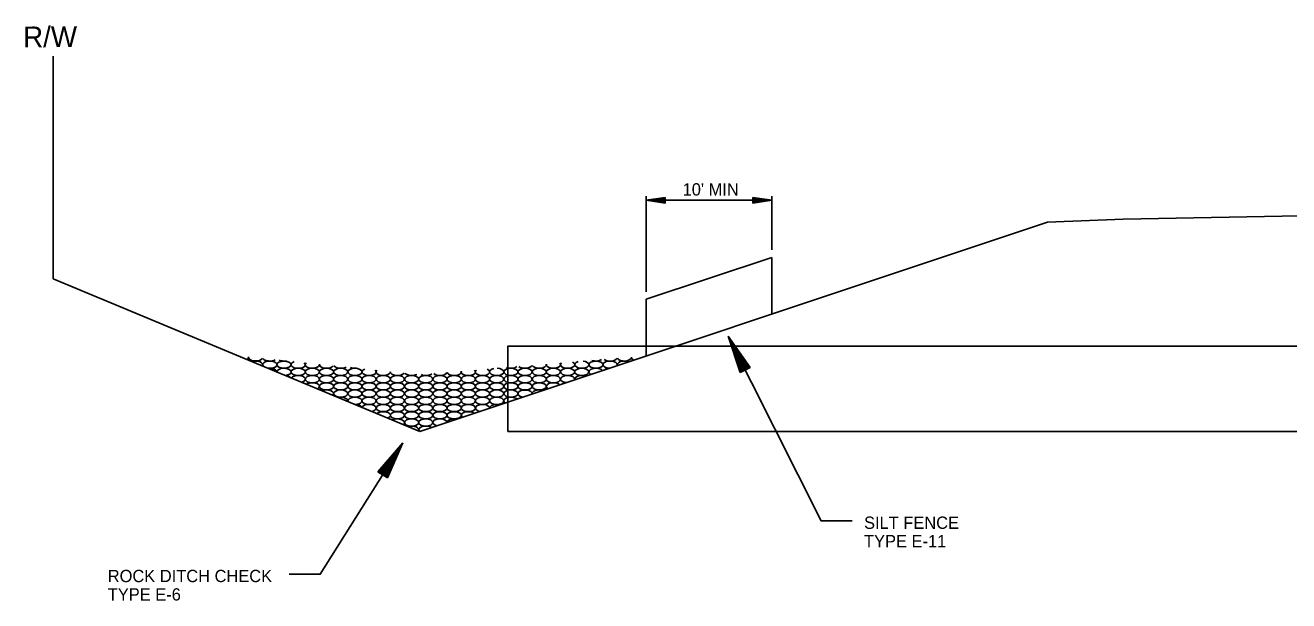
# Model space of a CAD drawing. Extents: x 3575 to 11445, y 9479 to 13278.
# Drawn here: x 3575 to 4243, y 12956 to 13260 of the extents above; entities that cross this region are included whole.
import ezdxf

# ---------------------------------------------------------------- set-up
doc = ezdxf.new("R2010")
doc.units = 0
for name, color, linetype in [('Agg Base Course Text', 7, 'Continuous'), ('Aggregate Base Course', 7, 'Continuous'), ('Default', 7, 'Continuous'), ('R_Culvert', 7, 'Continuous'), ('R_Dimension', 7, 'Continuous'), ('R_ROW', 7, 'Continuous'), ('R_ROW Annot Labels', 7, 'Continuous'), ('STAMP_PE_CRAFTON-SIGNATURE', 7, 'Continuous')]:
    doc.layers.add(name, color=color, linetype=linetype)

msp = doc.modelspace()

# ---------------------------------------------------------------- linework, layer by layer
at = {"layer": 'Agg Base Course Text'}
for points in [[(4012.16, 12997.7), (3995.71, 12997.7), (3946.53, 13095.5)], [(3714.29, 12969.51), (3730.74, 12969.51), (3774.5, 13038.99)]]:
    msp.add_lwpolyline(points, dxfattribs=at)
at = {"layer": 'Aggregate Base Course'}
for centre, start_param, end_param in [((3689.08, 13084.23), 2.514604, 3.290239), ((3696.58, 13084.23), 6.138963, 9.16605), ((3891.58, 13084.23), 0.234109, 3.231422), ((3899.08, 13084.23), 6.192018, 7.124953), ((3899.08, 13084.23), 3.457622, 3.556698), ((3906.58, 13084.23), 5.83504, 5.875133), ((3696.58, 13080.41), 2.805024, 5.249722), ((3704.08, 13080.41), 1.278334, 6.776412), ((3704.08, 13084.23), 0.273657, 2.464986), ((3704.08, 13076.58), 3.131558, 4.923189), ((3711.58, 13076.58), 1.761439, 6.293307), ((3711.58, 13084.23), 0.829284, 1.909359), ((3719.08, 13080.41), 5.30404, 10.000973), ((3726.58, 13080.41), 5.775562, 9.529451), ((3734.08, 13080.41), 6.180718, 9.124295), ((3741.58, 13080.41), 0.321062, 2.417581), ((3749.08, 13080.41), 0.916722, 1.82192), ((3756.58, 13076.58), 5.360895, 9.944118), ((3764.08, 13076.58), 5.818933, 9.48608), ((3809.08, 13076.58), 6.111119, 9.920782), ((3816.58, 13076.58), 5.737074, 10.294828), ((3824.08, 13076.58), 5.107712, 10.924189), ((3831.58, 13080.41), 0.907562, 2.557968), ((3839.08, 13080.41), 0.525834, 2.939697), ((3846.58, 13080.41), 0.195345, 3.270186), ((3854.08, 13080.41), 6.151816, 9.880086), ((3861.58, 13080.41), 5.786986, 10.244916), ((3869.08, 13080.41), 5.239177, 10.792724), ((3876.58, 13076.58), 3.525059, 7.057516), ((3876.58, 13084.23), 0.961624, 2.503906), ((3884.08, 13080.41), 2.835165, 7.74741), ((3884.08, 13076.58), 4.840285, 5.74229), ((3884.08, 13084.23), 0.567598, 2.897933), ((3891.58, 13080.41), 4.046304, 6.536271), ((3711.58, 13072.76), 3.595841, 4.458905), ((3719.08, 13072.76), 2.091472, 5.963275), ((3726.58, 13068.93), 2.382906, 5.67184), ((3771.58, 13076.58), 6.222647, 9.082366), ((3779.08, 13076.58), 0.369799, 2.368843), ((3786.58, 13076.58), 0.856077, 2.609454), ((3794.08, 13076.58), 0.484724, 2.980806), ((3801.58, 13076.58), 0.15663, 3.3089), ((3854.08, 13068.93), 3.591606, 6.755501), ((3861.58, 13072.76), 2.933177, 7.649398), ((3861.58, 13068.93), 5.028509, 5.554066), ((3869.08, 13072.76), 4.116502, 6.466073), ((3734.08, 13065.11), 2.667988, 5.386758), ((3839.08, 13065.11), 3.022345, 7.56023), ((3846.58, 13065.11), 4.188827, 6.393748), ((3854.08, 13068.93), 0.472316, 0.707784), ((3741.58, 13061.28), 2.972437, 5.082309), ((3749.08, 13061.28), 1.574453, 6.480293), ((3749.08, 13057.46), 3.34603, 4.708717), ((3756.58, 13057.46), 1.946039, 6.108707), ((3816.58, 13057.46), 3.105273, 7.477302), ((3824.08, 13057.46), 4.263908, 6.318667), ((3831.58, 13061.28), 3.657582, 6.924993), ((3764.08, 13053.63), 2.249906, 5.80484), ((3771.58, 13049.81), 2.534898, 5.519849), ((3794.08, 13049.81), 3.18359, 7.398985), ((3801.58, 13049.81), 4.34257, 6.240005), ((3809.08, 13053.63), 3.723285, 6.85929), ((3779.08, 13045.98), 2.826651, 5.228095), ((3786.58, 13045.98), 3.789, 6.726478)]:
    msp.add_ellipse(centre, major_axis=(-3.75, 0), ratio=0.51, start_param=start_param, end_param=end_param, dxfattribs=at)
for centre in [(3711.58, 13080.41), (3719.08, 13076.58), (3726.58, 13076.58), (3734.08, 13076.58), (3741.58, 13076.58), (3749.08, 13076.58), (3831.58, 13076.58), (3839.08, 13076.58), (3846.58, 13076.58), (3854.08, 13076.58), (3861.58, 13076.58), (3869.08, 13076.58), (3876.58, 13080.41), (3726.58, 13072.76), (3734.08, 13072.76), (3734.08, 13068.93), (3741.58, 13072.76), (3741.58, 13068.93), (3749.08, 13072.76), (3749.08, 13068.93), (3756.58, 13072.76), (3756.58, 13068.93), (3764.08, 13072.76), (3764.08, 13068.93), (3771.58, 13072.76), (3771.58, 13068.93), (3779.08, 13072.76), (3779.08, 13068.93), (3786.58, 13072.76), (3786.58, 13068.93), (3794.08, 13072.76), (3794.08, 13068.93), (3801.58, 13072.76), (3801.58, 13068.93), (3809.08, 13072.76), (3809.08, 13068.93), (3816.58, 13072.76), (3816.58, 13068.93), (3824.08, 13072.76), (3824.08, 13068.93), (3831.58, 13072.76), (3831.58, 13068.93), (3839.08, 13072.76), (3839.08, 13068.93), (3846.58, 13072.76), (3846.58, 13068.93), (3854.08, 13072.76), (3741.58, 13065.11), (3749.08, 13065.11), (3756.58, 13065.11), (3764.08, 13065.11), (3771.58, 13065.11), (3779.08, 13065.11), (3786.58, 13065.11), (3794.08, 13065.11), (3801.58, 13065.11), (3809.08, 13065.11), (3816.58, 13065.11), (3824.08, 13065.11), (3831.58, 13065.11), (3756.58, 13061.28), (3764.08, 13061.28), (3764.08, 13057.46), (3771.58, 13061.28), (3771.58, 13057.46), (3779.08, 13061.28), (3779.08, 13057.46), (3786.58, 13061.28), (3786.58, 13057.46), (3794.08, 13061.28), (3794.08, 13057.46), (3801.58, 13061.28), (3801.58, 13057.46), (3809.08, 13061.28), (3809.08, 13057.46), (3816.58, 13061.28), (3824.08, 13061.28), (3771.58, 13053.63), (3779.08, 13053.63), (3779.08, 13049.81), (3786.58, 13053.63), (3786.58, 13049.81), (3794.08, 13053.63), (3801.58, 13053.63)]:
    msp.add_ellipse(centre, major_axis=(-3.75, 0), ratio=0.51, dxfattribs=at)
at = {"layer": 'Default'}
for p, q in [((4265.38, 13159.56), (4155.4, 13157.36)), ((3783.4, 13045.08), (4115.44, 13155.76)), ((4155.4, 13157.36), (4115.44, 13155.76)), ((3969.62, 13137.15), (3969.62, 13107.15)), ((3783.4, 13045.08), (3589.55, 13125.85))]:
    msp.add_line(p, q, dxfattribs=at)
msp.add_lwpolyline([(3903.21, 13085.02), (3903.21, 13115.02), (3969.62, 13137.15)], dxfattribs=at)
at = {"layer": 'R_Culvert'}
msp.add_lwpolyline([(3830, 13045.08), (4700.77, 13045.08), (4700.77, 13090.24), (3830, 13090.24)], close=True, dxfattribs=at)
at = {"layer": 'R_Dimension'}
for p, q in [((3903.21, 13119.02), (3903.21, 13169.64)), ((3913.21, 13168.87), (3903.21, 13167.37)), ((3903.21, 13167.37), (3969.62, 13167.37)), ((3913.21, 13165.87), (3903.21, 13167.37)), ((3913.21, 13168.62), (3904.88, 13167.37)), ((3913.21, 13166.12), (3904.88, 13167.37)), ((3913.21, 13168.36), (3906.6, 13167.37)), ((3913.21, 13166.37), (3906.6, 13167.37)), ((3913.21, 13168.11), (3908.26, 13167.37)), ((3913.21, 13166.62), (3908.26, 13167.37)), ((3913.21, 13167.86), (3909.96, 13167.37)), ((3913.21, 13166.88), (3909.96, 13167.37)), ((3913.21, 13167.6), (3911.63, 13167.37)), ((3913.21, 13167.13), (3911.63, 13167.37)), ((3913.21, 13165.87), (3913.21, 13168.87)), ((3959.62, 13168.87), (3969.62, 13167.37)), ((3959.62, 13168.87), (3959.62, 13165.87)), ((3959.62, 13168.62), (3967.95, 13167.37)), ((3959.62, 13168.36), (3966.23, 13167.37)), ((3959.62, 13168.11), (3964.56, 13167.37)), ((3959.62, 13167.85), (3962.87, 13167.37)), ((3959.62, 13167.6), (3961.2, 13167.37)), ((3959.62, 13165.87), (3969.62, 13167.37)), ((3959.62, 13166.88), (3962.87, 13167.37)), ((3959.62, 13166.37), (3966.23, 13167.37)), ((3959.62, 13166.12), (3967.95, 13167.37)), ((3959.62, 13166.62), (3964.56, 13167.37)), ((3959.62, 13167.13), (3961.2, 13167.37)), ((3969.62, 13169.64), (3969.62, 13141.15))]:
    msp.add_line(p, q, dxfattribs=at)
at = {"layer": 'R_ROW'}
msp.add_line((3589.55, 13125.85), (3589.55, 13243.58), dxfattribs=at)
at = {"layer": 'STAMP_PE_CRAFTON-SIGNATURE'}
for p, q in [((3952.83, 13076.28), (3946.53, 13095.5)), ((3958.19, 13078.98), (3946.53, 13095.5)), ((3953.28, 13076.51), (3948.03, 13092.51)), ((3957.75, 13078.75), (3948.03, 13092.51)), ((3957.29, 13078.52), (3949.57, 13089.44)), ((3953.74, 13076.73), (3949.57, 13089.44)), ((3954.18, 13076.96), (3951.07, 13086.46)), ((3956.84, 13078.3), (3951.07, 13086.46)), ((3956.39, 13078.07), (3952.59, 13083.44)), ((3954.65, 13077.19), (3952.59, 13083.44)), ((3952.83, 13076.28), (3958.19, 13078.98)), ((3955.93, 13077.84), (3954.09, 13080.45)), ((3955.09, 13077.42), (3954.09, 13080.45)), ((3761.3, 13023.67), (3774.5, 13038.99)), ((3766.38, 13020.47), (3774.5, 13038.99)), ((3761.73, 13023.4), (3772.72, 13036.16)), ((3762.16, 13023.13), (3770.89, 13033.25)), ((3762.58, 13022.86), (3769.11, 13030.44)), ((3765.1, 13021.27), (3769.11, 13030.44)), ((3765.52, 13021.01), (3770.89, 13033.25)), ((3765.96, 13020.73), (3772.72, 13036.16)), ((3763.01, 13022.59), (3767.3, 13027.57)), ((3763.44, 13022.32), (3765.52, 13024.74)), ((3764.24, 13021.82), (3765.52, 13024.74)), ((3764.66, 13021.55), (3767.3, 13027.57)), ((3766.38, 13020.47), (3761.3, 13023.67))]:
    msp.add_line(p, q, dxfattribs=at)

# ---------------------------------------------------------------- texts
at = {"layer": 'Agg Base Course Text'}
for s, p in [('SILT FENCE', (4018.36, 12993.55)), ('TYPE E-11', (4018.36, 12983.8)), ('ROCK DITCH CHECK', (3618.38, 12965.36)), ('TYPE E-6', (3618.38, 12955.61))]:
    msp.add_text(s, height=6.5, dxfattribs=at).set_placement(p)
at = {"layer": 'R_Dimension'}
msp.add_text("10' MIN", height=6.5, dxfattribs=at).set_placement((3922.42, 13169.9))
at = {"layer": 'R_ROW Annot Labels'}
msp.add_text('R/W', height=11, rotation=0.43502, dxfattribs=at).set_placement((3573.63, 13248.28))

doc.saveas('drawing.dxf')
